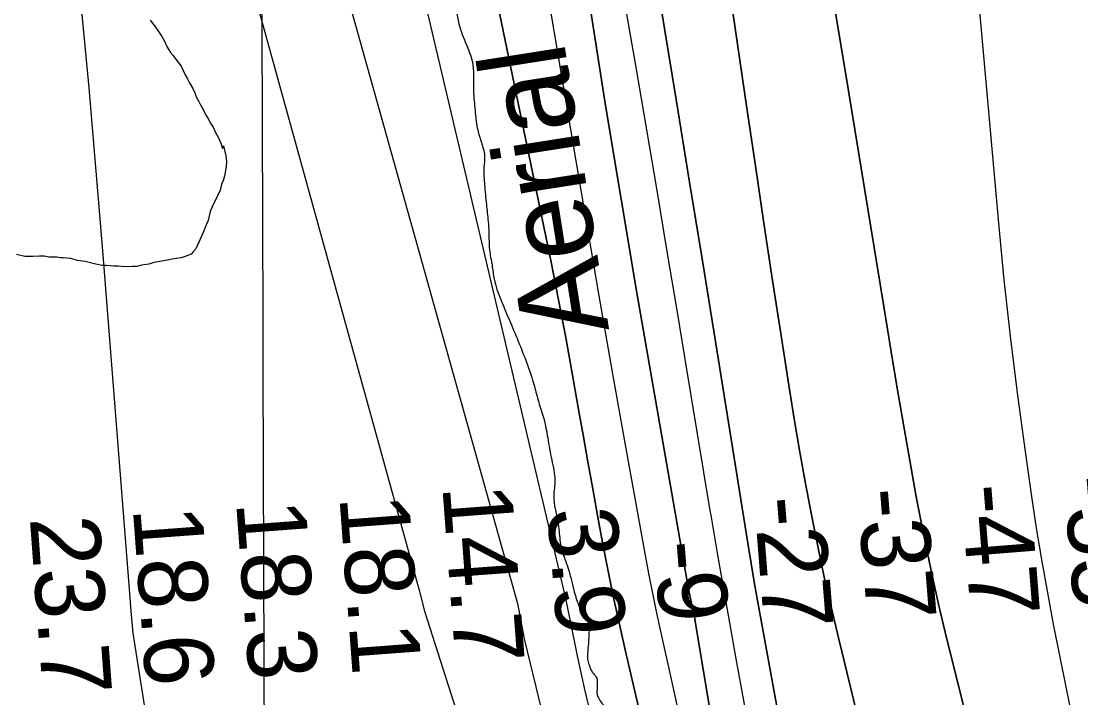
# Model space of a CAD drawing. Extents: x 3392644 to 3430565, y 576657 to 602123.
# Drawn here: x 3401788 to 3402813, y 589627 to 590281 of the extents above; entities that cross this region are included whole.
import ezdxf

# ---------------------------------------------------------------- set-up
doc = ezdxf.new("R2010")
doc.units = 0
for name, color, linetype in [('V-GRID-MAJR', 7, 'Continuous'), ('V-RIVR-EDGE', 7, 'Continuous'), ('V-RIVR-IDEN', 7, 'Continuous'), ('V-RIVR-RANG', 7, 'Continuous'), ('V-SITE-VEGE', 7, 'Continuous'), ('V-TOPO-DPTH', 7, 'Continuous'), ('V-TOPO-MAJR', 7, 'Continuous'), ('V-TOPO-MINR', 7, 'Continuous'), ('V-TOPO-WATR', 7, 'Continuous')]:
    doc.layers.add(name, color=color, linetype=linetype)

msp = doc.modelspace()

# ---------------------------------------------------------------- linework, layer by layer
at = {"layer": 'V-GRID-MAJR'}
msp.add_spline([(3402048.6720000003, 582063.4890000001), (3402028.4020000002, 588122.6730000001), (3402008.125, 594183.791), (3401987.849, 600244.93), (3401987.843, 600246.845)], degree=3, dxfattribs=at)
at = {"layer": 'V-RIVR-EDGE'}
for points in [[(3402169.908173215, 590490.0269484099), (3402177.270544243, 590474.8566021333), (3402182.8701778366, 590459.3382392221), (3402189.5103760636, 590437.122171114), (3402194.3817376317, 590412.0914738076), (3402196.7917145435, 590389.1811150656), (3402197.107492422, 590374.3805683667), (3402199.180779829, 590357.8137989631), (3402202.9897938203, 590330.6714762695), (3402207.4983263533, 590301.4131716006), (3402212.367945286, 590275.6777278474), (3402219.3692299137, 590256.9845206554), (3402224.268473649, 590243.2297664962), (3402225.6457277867, 590230.1884719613), (3402225.599547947, 590211.5126911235)], [(3402225.599547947, 590211.5126911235), (3402227.3152342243, 590192.8325536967), (3402229.7408948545, 590176.2649129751), (3402233.235002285, 590164.2755102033), (3402236.3741225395, 590151.2298590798), (3402235.6414939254, 590139.955658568), (3402236.304417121, 590123.0400012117), (3402238.0201033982, 590104.3598637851), (3402239.741017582, 590087.7939656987), (3402240.418753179, 590076.8686531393), (3402241.08341901, 590060.6577422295), (3402243.512564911, 590045.4995944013), (3402245.593694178, 590032.1041840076), (3402251.8876184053, 590012.3555997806), (3402259.9451513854, 589993.3074054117), (3402277.106881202, 589950.9799240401), (3402284.451825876, 589928.7621132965), (3402288.641966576, 589913.2472356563), (3402293.5359824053, 589897.378242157), (3402297.3659080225, 589878.6928768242), (3402301.188863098, 589857.1885257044), (3402304.3114283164, 589837.4477833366), (3402303.2177133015, 589822.6507219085), (3402304.5958387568, 589809.9618005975), (3402308.071648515, 589790.5725601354), (3402310.1440646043, 589773.6534175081), (3402313.989673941, 589761.3107701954), (3402317.139250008, 589752.4935977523), (3402320.281855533, 589740.857439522), (3402323.07383047, 589729.9268990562), (3402325.169772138, 589722.5218334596), (3402328.3210908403, 589714.4094074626), (3402332.5269152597, 589705.2372478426), (3402337.4409713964, 589697.4728384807), (3402337.4322582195, 589693.9491062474), (3402336.6926590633, 589679.8559199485), (3402335.9635157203, 589669.9912123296), (3402335.9574164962, 589667.524599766), (3402335.950445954, 589664.7056139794), (3402337.346869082, 589659.4165303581), (3402338.745906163, 589655.184566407), (3402342.6080705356, 589649.537010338), (3402345.0642272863, 589645.3024324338), (3402345.05551411, 589641.7787002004), (3402345.038087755, 589634.7312357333), (3402345.0293745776, 589631.2075034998), (3402346.4292829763, 589627.327912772), (3402349.5884435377, 589622.3868457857), (3402353.807337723, 589618.5002845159)]]:
    msp.add_spline(points, degree=3, dxfattribs=at)
at = {"layer": 'V-SITE-VEGE'}
msp.add_lwpolyline([(3401913.171, 590282.452), (3401919.125, 590274.4670000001), (3401924.148, 590266.4940000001), (3401927.343, 590261.339), (3401929.608, 590256.1900000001), (3401932.803, 590251.034), (3401935.097, 590248.214), (3401937.3850000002, 590244.929), (3401940.592, 590240.704), (3401942.883, 590237.881), (3401946.971, 590229.458), (3401949.253, 590225.706), (3401951.069, 590221.96), (3401954.258, 590216.336), (3401956.071, 590212.13), (3401957.42, 590208.388), (3401960.156, 590203.702), (3401961.975, 590199.959), (3401964.254, 590196.211), (3401966.98, 590190.591), (3401969.262, 590186.839), (3401971.078, 590183.095), (3401973.821, 590178.8740000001), (3401975.6350000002, 590175.131), (3401979.274, 590168.106), (3401981.5330000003, 590162.4940000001), (3401982.881, 590158.29), (3401983.843, 590161.069), (3401985.173, 590155.47), (3401986.053, 590151.2710000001), (3401986.915, 590145.676), (3401986.395, 590141.029), (3401984.8880000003, 590131.74), (3401983.44, 590127.5700000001), (3401982, 590123.863), (3401980.532, 590117.832), (3401978.625, 590114.131), (3401977.185, 590110.424), (3401974.326, 590104.8740000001), (3401970.98, 590097.47), (3401969.012, 590088.652), (3401966.62, 590083.096), (3401964.22, 590077.074), (3401957.049, 590061.34), (3401954.219, 590058.1140000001), (3401952.802, 590056.2710000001), (3401946.723, 590054.0160000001), (3401943.9220000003, 590053.1190000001), (3401940.653, 590052.228), (3401934.126, 590051.376), (3401929.928, 590050.496), (3401916.407, 590048.331), (3401911.731, 590046.526), (3401904.742, 590045.679), (3401900.537, 590044.335), (3401895.884, 590044.39), (3401887.501, 590044.026), (3401882.39, 590044.552), (3401877.737, 590044.608), (3401870.7630000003, 590045.156), (3401866.575, 590045.208), (3401860.544, 590046.676), (3401850.3340000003, 590049.125), (3401842.9, 590050.145), (3401835.943, 590052.091), (3401828.97, 590052.64), (3401826.643, 590052.6680000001), (3401822.928, 590053.178), (3401815.017, 590053.273), (3401810.841, 590054.254), (3401806.188, 590054.311), (3401799.667, 590053.924), (3401795.946, 590053.969), (3401791.757, 590054.018), (3401783.869, 590055.974)], dxfattribs=at)
at = {"layer": 'V-TOPO-DPTH'}
for points in [[(3401983.2324119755, 590968.6679456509), (3401990.1753502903, 590884.6576055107), (3401999.4954309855, 590800.8776691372), (3402010.400273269, 590717.2513352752), (3402030.3982368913, 590579.1808770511), (3402032.694975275, 590564.7437197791), (3402035.258030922, 590550.3578455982), (3402268.230022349, 589718.4169068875), (3402274.4846897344, 589684.2706644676), (3402439.6848734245, 589005.6338973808), (3402443.7939876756, 588979.9680700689), (3402446.98534152, 588954.2132787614), (3402448.800054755, 588928.3250414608), (3402356.816492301, 588119.580552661)], [(3402365.47655252, 590547.1040639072), (3402421.4570020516, 590205.6760027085), (3402434.2010294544, 590127.6855260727), (3402446.888858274, 590049.6859390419), (3402459.4923892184, 589971.6726864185), (3402472.039721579, 589893.6503234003), (3402490.7613715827, 589776.8319403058), (3402493.970906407, 589757.2231243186), (3402497.267334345, 589737.6292245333), (3402500.6941019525, 589718.0576990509), (3402504.2077626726, 589698.5010897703), (3402549.779232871, 589449.6175808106)], [(3402549.779232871, 589449.6175808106), (3402504.2077626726, 589698.5010897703), (3402500.6941019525, 589718.0576990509), (3402497.267334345, 589737.6292245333), (3402493.970906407, 589757.2231243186), (3402490.7613715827, 589776.8319403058), (3402472.039721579, 589893.6503234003), (3402459.4923892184, 589971.6726864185), (3402446.888858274, 590049.6859390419), (3402434.2010294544, 590127.6855260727), (3402421.4570020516, 590205.6760027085), (3402365.47655252, 590547.1040639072)], [(3402223.9148138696, 590418.212562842), (3402300.667923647, 590048.5866816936), (3402307.7843204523, 590012.1606530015), (3402314.7251346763, 589975.7018542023), (3402321.4025750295, 589939.1939002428), (3402327.9044328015, 589902.6531761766), (3402331.559559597, 589881.6723953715), (3402336.1549234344, 589855.6070424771), (3402340.820647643, 589829.5544375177), (3402345.5919124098, 589803.5209544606), (3402350.4335375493, 589777.5002193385), (3402355.4910645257, 589751.5233005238), (3402360.766017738, 589725.5920382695), (3402366.3671103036, 589699.7292608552), (3402372.1856291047, 589673.9121400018), (3402398.529094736, 589560.3631647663)], [(3402398.529094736, 589560.3631647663), (3402372.1856291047, 589673.9121400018), (3402366.3671103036, 589699.7292608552), (3402360.766017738, 589725.5920382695), (3402355.4910645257, 589751.5233005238), (3402350.4335375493, 589777.5002193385), (3402345.5919124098, 589803.5209544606), (3402340.820647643, 589829.5544375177), (3402336.1549234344, 589855.6070424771), (3402331.559559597, 589881.6723953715), (3402327.9044328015, 589902.6531761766), (3402321.4025750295, 589939.1939002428), (3402314.7251346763, 589975.7018542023), (3402307.7843204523, 590012.1606530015), (3402300.667923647, 590048.5866816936), (3402223.9148138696, 590418.212562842)], [(3402469.823126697, 590334.6352105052), (3402489.9257230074, 590197.1958148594), (3402498.1114294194, 590141.7255240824), (3402506.3915022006, 590086.2694461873), (3402514.813124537, 590030.8346876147), (3402523.329113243, 589975.4141419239), (3402531.0793317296, 589925.4024385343), (3402535.965061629, 589895.0288030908), (3402541.0828201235, 589864.6956869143), (3402546.548621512, 589834.423349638), (3402552.246451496, 589804.1915316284), (3402558.3403572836, 589774.0389759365), (3402564.7301151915, 589743.951538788), (3402571.56365128, 589713.9617794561), (3402578.693039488, 589684.0371386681), (3402604.4054201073, 589579.5429661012)], [(3402604.4054201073, 589579.5429661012), (3402578.693039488, 589684.0371386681), (3402571.56365128, 589713.9617794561), (3402564.7301151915, 589743.951538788), (3402558.3403572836, 589774.0389759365), (3402552.246451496, 589804.1915316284), (3402546.548621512, 589834.423349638), (3402541.0828201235, 589864.6956869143), (3402535.965061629, 589895.0288030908), (3402531.0793317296, 589925.4024385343), (3402523.329113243, 589975.4141419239), (3402514.813124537, 590030.8346876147), (3402506.3915022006, 590086.2694461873), (3402498.1114294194, 590141.7255240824), (3402489.9257230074, 590197.1958148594), (3402469.823126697, 590334.6352105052)], [(3402571.839069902, 590313.075304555), (3402584.837502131, 590233.8169605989), (3402594.1857287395, 590176.786397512), (3402603.527681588, 590119.7548072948), (3402612.8602237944, 590062.7216763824), (3402622.1864922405, 590005.6875183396), (3402629.354074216, 589961.8319418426), (3402635.1976587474, 589926.7431903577), (3402641.182314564, 589891.6789550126), (3402647.3785773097, 589856.6514938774), (3402653.715911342, 589821.6485488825), (3402653.997308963, 589820.1206353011), (3402660.610907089, 589785.9672052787), (3402667.63905146, 589751.9032653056), (3402675.2890152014, 589717.9735604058), (3402683.353525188, 589684.1333455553), (3402706.9269248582, 589589.0786933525)], [(3402571.839069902, 590313.075304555), (3402584.837502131, 590233.8169605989), (3402594.1857287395, 590176.786397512), (3402603.527681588, 590119.7548072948), (3402612.8602237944, 590062.7216763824), (3402622.1864922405, 590005.6875183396), (3402629.354074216, 589961.8319418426), (3402635.1976587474, 589926.7431903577), (3402641.182314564, 589891.6789550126), (3402647.3785773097, 589856.6514938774), (3402653.715911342, 589821.6485488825), (3402653.997308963, 589820.1206353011), (3402660.610907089, 589785.9672052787), (3402667.63905146, 589751.9032653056), (3402675.2890152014, 589717.9735604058), (3402683.353525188, 589684.1333455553), (3402706.9269248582, 589589.0786933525)], [(3402552.2278107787, 589027.126557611), (3402439.958216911, 589701.0766836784), (3402439.4439264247, 589704.0326975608), (3402438.9013970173, 589706.9833090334), (3402438.316509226, 589709.9258168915), (3402437.703382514, 589712.8629223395), (3402437.0693029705, 589715.7960251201), (3402436.4355387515, 589718.7291960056), (3402435.8022475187, 589721.6624690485), (3402435.16927161, 589724.5958101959), (3402434.4611968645, 589727.878458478), (3402433.4827505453, 589732.7771916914), (3402433.1870593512, 589734.416038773), (3402383.6292648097, 590018.8259795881), (3402368.2341332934, 590109.3465517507), (3402353.3290655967, 590199.9457083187), (3402339.159093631, 590290.6627414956)], [(3402552.2278107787, 589027.126557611), (3402439.958216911, 589701.0766836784), (3402439.4439264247, 589704.0326975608), (3402438.9013970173, 589706.9833090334), (3402438.316509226, 589709.9258168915), (3402437.703382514, 589712.8629223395), (3402437.0693029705, 589715.7960251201), (3402436.4355387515, 589718.7291960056), (3402435.8022475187, 589721.6624690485), (3402435.16927161, 589724.5958101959), (3402434.4611968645, 589727.878458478), (3402433.4827505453, 589732.7771916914), (3402433.1870593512, 589734.416038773), (3402383.6292648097, 590018.8259795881), (3402368.2341332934, 590109.3465517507), (3402353.3290655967, 590199.9457083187), (3402339.159093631, 590290.6627414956)]]:
    msp.add_lwpolyline(points, dxfattribs=at)
at = {"layer": 'V-TOPO-MAJR'}
msp.add_lwpolyline([(3402811.0013850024, 589574.9739549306), (3402798.9128169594, 589636.3194171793), (3402786.4733180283, 589698.572373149), (3402780.689725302, 589728.8028692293), (3402775.2373893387, 589759.0902010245), (3402770.281938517, 589789.4627863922), (3402765.6577444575, 589819.8922074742), (3402758.7759854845, 589867.8174313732), (3402751.3999859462, 589922.3033309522), (3402744.610935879, 589976.8574738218), (3402738.702310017, 590031.513981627), (3402733.3806336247, 590086.2387327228), (3402695.571573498, 590510.5253860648), (3402692.3134362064, 590547.3791651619), (3402689.089671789, 590584.2359265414), (3402685.917466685, 590621.0971613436), (3402682.7796344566, 590657.961378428), (3402681.988514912, 590667.333255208), (3402678.794508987, 590708.9042059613), (3402676.0184252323, 590750.499888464), (3402673.869224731, 590792.132668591), (3402672.1379464, 590833.7901804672), (3402658.1828608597, 591244.0353686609)], dxfattribs=at)
at = {"layer": 'V-TOPO-MINR'}
for points in [[(3401936.680185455, 591031.3200367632), (3401939.044525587, 590935.1207899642), (3401941.2601198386, 590838.9180024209), (3401943.3765501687, 590742.7128543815), (3401947.2046294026, 590562.3615172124), (3401947.432742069, 590554.1671924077), (3401947.733002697, 590545.975989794), (3402173.1077528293, 589731.3317674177), (3402178.1472349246, 589711.3207787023), (3402400.0589522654, 589018.2294907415), (3402401.8446181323, 589011.4077743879), (3402403.357249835, 589004.5056818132), (3402410.2584788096, 588967.715218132), (3402411.514057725, 588959.8725564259), (3402412.4892003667, 588952.0027114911), (3402413.043688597, 588944.0920917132), (3402320.7812215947, 588156.1759327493)], [(3401783.3508998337, 590997.885167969), (3401789.683309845, 590906.1667832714), (3401797.028580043, 590814.5239520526), (3401805.0490903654, 590722.9314898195), (3401818.20864063, 590581.6383566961), (3401820.178450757, 590560.7324256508), (3401822.1782628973, 590539.8293975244), (3401824.223078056, 590518.9307237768), (3401826.297895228, 590498.0349529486), (3401838.2976932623, 590378.4923784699), (3401846.1330074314, 590297.8040644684), (3401853.619150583, 590217.0845093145), (3401860.58153721, 590136.3180924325), (3401867.1947528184, 590055.520434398), (3401892.587545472, 589732.3945569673), (3401894.3767023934, 589711.1015344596), (3401896.3191168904, 589689.8233379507), (3402014.2872907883, 588943.2527003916)], [(3401983.2324119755, 590968.6679456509), (3401990.1753502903, 590884.6576055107), (3401999.4954309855, 590800.8776691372), (3402010.400273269, 590717.2513352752), (3402030.3982368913, 590579.1808770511), (3402032.694975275, 590564.7437197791), (3402035.258030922, 590550.3578455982), (3402268.230022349, 589718.4169068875), (3402274.4846897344, 589684.2706644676), (3402439.6848734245, 589005.6338973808), (3402443.7939876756, 588979.9680700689), (3402446.98534152, 588954.2132787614), (3402448.800054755, 588928.3250414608), (3402356.816492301, 588119.580552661)], [(3402035.2523009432, 590938.4310933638), (3402042.638547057, 590898.2338251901), (3402050.6078128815, 590858.1480695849), (3402058.9657585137, 590818.1366556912), (3402067.662495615, 590778.1914244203), (3402076.422084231, 590738.260058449), (3402085.27595012, 590698.3494904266), (3402094.1926675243, 590658.452787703), (3402107.4830322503, 590599.314902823), (3402112.667992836, 590576.8350316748), (3402118.0209276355, 590554.3962314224), (3402123.625823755, 590532.0190375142), (3402129.398694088, 590509.6829145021), (3402314.967871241, 589722.0039368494), (3402317.1774762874, 589710.9680229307), (3402319.4037851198, 589699.9354337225), (3402326.2408264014, 589666.2513266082), (3402329.6393938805, 589650.1656333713), (3402333.207985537, 589634.1191751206), (3402337.031613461, 589618.1315693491)], [(3402365.47655252, 590547.1040639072), (3402421.4570020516, 590205.6760027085), (3402434.2010294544, 590127.6855260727), (3402446.888858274, 590049.6859390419), (3402459.4923892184, 589971.6726864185), (3402472.039721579, 589893.6503234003), (3402490.7613715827, 589776.8319403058), (3402493.970906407, 589757.2231243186), (3402497.267334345, 589737.6292245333), (3402500.6941019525, 589718.0576990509), (3402504.2077626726, 589698.5010897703), (3402549.779232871, 589449.6175808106)], [(3402278.549308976, 590418.9920053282), (3402322.1771919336, 590159.7720269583), (3402334.4159581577, 590087.8023780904), (3402346.8178742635, 590015.861140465), (3402359.464515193, 589943.9625197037), (3402372.274306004, 589872.0923101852), (3402391.219991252, 589766.8332488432), (3402394.798080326, 589747.637802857), (3402398.5344799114, 589728.4742439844), (3402402.5083452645, 589709.3585157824), (3402406.640521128, 589690.2746746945), (3402416.0102628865, 589648.2637223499), (3402422.8874266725, 589617.5512634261)], [(3402469.823126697, 590334.6352105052), (3402489.9257230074, 590197.1958148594), (3402498.1114294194, 590141.7255240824), (3402506.3915022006, 590086.2694461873), (3402514.813124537, 590030.8346876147), (3402523.329113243, 589975.4141419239), (3402531.0793317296, 589925.4024385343), (3402535.965061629, 589895.0288030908), (3402541.0828201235, 589864.6956869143), (3402546.548621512, 589834.423349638), (3402552.246451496, 589804.1915316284), (3402558.3403572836, 589774.0389759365), (3402564.7301151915, 589743.951538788), (3402571.56365128, 589713.9617794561), (3402578.693039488, 589684.0371386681), (3402604.4054201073, 589579.5429661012)], [(3402706.9269248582, 589589.0786933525), (3402683.353525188, 589684.1333455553), (3402675.2890152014, 589717.9735604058), (3402667.63905146, 589751.9032653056), (3402660.610907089, 589785.9672052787), (3402653.997308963, 589820.1206353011), (3402653.715911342, 589821.6485488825), (3402647.3785773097, 589856.6514938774), (3402641.182314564, 589891.6789550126), (3402635.1976587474, 589926.7431903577), (3402629.354074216, 589961.8319418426), (3402622.1864922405, 590005.6875183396), (3402612.8602237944, 590062.7216763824), (3402603.527681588, 590119.7548072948), (3402594.1857287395, 590176.786397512), (3402584.837502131, 590233.8169605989), (3402571.839069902, 590313.075304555)], [(3402339.159093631, 590290.6627414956), (3402353.3290655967, 590199.9457083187), (3402368.2341332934, 590109.3465517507), (3402383.6292648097, 590018.8259795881), (3402433.1870593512, 589734.416038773), (3402433.4827505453, 589732.7771916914), (3402434.4611968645, 589727.878458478), (3402435.16927161, 589724.5958101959), (3402435.8022475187, 589721.6624690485), (3402436.4355387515, 589718.7291960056), (3402437.0693029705, 589715.7960251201), (3402437.703382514, 589712.8629223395), (3402438.316509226, 589709.9258168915), (3402438.9013970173, 589706.9833090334), (3402439.4439264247, 589704.0326975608), (3402439.958216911, 589701.0766836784), (3402552.2278107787, 589027.126557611)], [(3402373.5426414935, 590288.2973494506), (3402382.7195201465, 590235.1785017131), (3402392.7978972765, 590176.4419873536), (3402402.7868615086, 590117.6903759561), (3402412.641706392, 590058.9161190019), (3402422.407138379, 590000.12676501), (3402429.5868241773, 589956.5967368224), (3402435.708898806, 589919.5633252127), (3402441.849034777, 589882.5329152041), (3402448.0162627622, 589845.5070075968), (3402454.2015520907, 589808.4841015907), (3402454.9807119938, 589803.8308065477), (3402460.8724482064, 589769.1512838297), (3402466.874153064, 589734.4910728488), (3402473.0408108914, 589699.859829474), (3402479.317437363, 589665.2478978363), (3402584.0209856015, 589095.5963246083)]]:
    msp.add_lwpolyline(points, dxfattribs=at)
at = {"layer": 'V-TOPO-WATR'}
msp.add_lwpolyline([(3402223.9148138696, 590418.212562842), (3402300.667923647, 590048.5866816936), (3402307.7843204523, 590012.1606530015), (3402314.7251346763, 589975.7018542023), (3402321.4025750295, 589939.1939002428), (3402327.9044328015, 589902.6531761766), (3402331.559559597, 589881.6723953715), (3402336.1549234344, 589855.6070424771), (3402340.820647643, 589829.5544375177), (3402345.5919124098, 589803.5209544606), (3402350.4335375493, 589777.5002193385), (3402355.4910645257, 589751.5233005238), (3402360.766017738, 589725.5920382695), (3402366.3671103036, 589699.7292608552), (3402372.1856291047, 589673.9121400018), (3402398.529094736, 589560.3631647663)], dxfattribs=at)

# ---------------------------------------------------------------- texts
at = {"layer": 'V-RIVR-IDEN'}
msp.add_text('Aerial ', height=83.00000000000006, rotation=98.91866062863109, dxfattribs=at).set_placement((3402356.7732411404, 589983.2504745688))
at = {"layer": 'V-RIVR-RANG'}
for s, height, rotation, p in [('-55', 67.00000000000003, 274.5376111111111, (3402796.015892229, 589841.1750004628)), ('14.7', 66.9999999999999, 274.2583257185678, (3402195.445542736, 589831.943613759)), ('-47', 67.00000000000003, 274.5376111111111, (3402696.394366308, 589832.4581894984)), ('18.1', 66.9999999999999, 274.2583257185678, (3402095.91582148, 589821.912151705)), ('-27', 67.00000000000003, 274.5376111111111, (3402496.7319440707, 589820.2846223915)), ('-37', 67.00000000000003, 274.5376111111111, (3402596.3962070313, 589828.4755278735)), ('18.3', 66.9999999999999, 274.2583257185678, (3401996.033542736, 589816.6146137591)), ('3.9', 67.00000000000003, 274.5376111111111, (3402296.9651792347, 589809.4248189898)), ('23.7', 66.9999999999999, 274.2583257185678, (3401796.621542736, 589801.284613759)), ('18.6', 66.9999999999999, 274.2583257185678, (3401896.1904370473, 589810.7909731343)), ('-9', 67.00000000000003, 274.5376111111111, (3402399.801457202, 589777.6469078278))]:
    msp.add_text(s, height=height, rotation=rotation, dxfattribs=at).set_placement(p)

doc.saveas('drawing.dxf')
